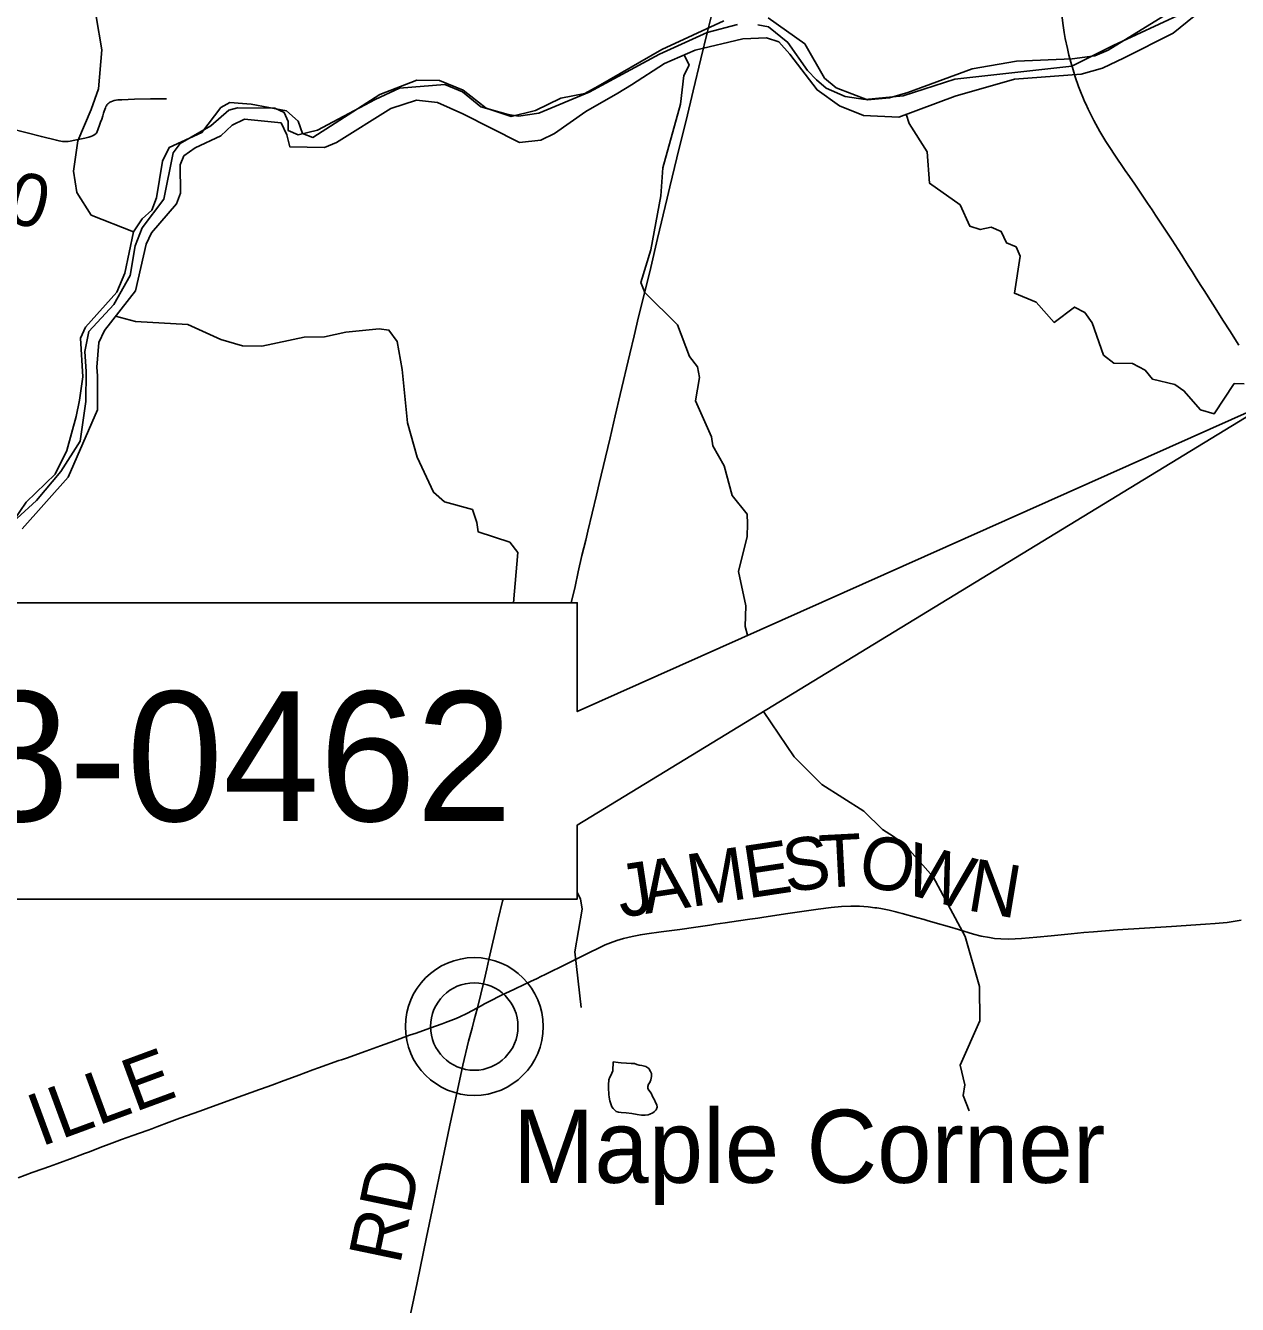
# Model space of a CAD drawing. Extents: x -1.4 to 35.4, y 0 to 22.
# Drawn here: x 13.799 to 15.107, y 13.734 to 15.116 of the extents above; entities that cross this region are included whole.
import ezdxf

# ---------------------------------------------------------------- set-up
doc = ezdxf.new("R2010")
doc.units = 0
for name, color, linetype in [('GM_X_County_Road', 7, 'Continuous'), ('GM_X_County_Road_Text', 7, 'Continuous'), ('GM_X_Major_River', 7, 'Continuous'), ('GM_X_Minor_Lake', 7, 'Continuous'), ('GM_X_Minor_River', 7, 'Continuous'), ('GM_X_Township_Road', 7, 'Continuous'), ('GM_X_Township_Road_Text', 7, 'Continuous'), ('GM_X_Unincorporated', 7, 'Continuous'), ('GM_X_Unincorporated_Location', 7, 'Continuous'), ('GM_X_Unincorporated_Text', 7, 'Continuous'), ('GM_X_US_Route', 7, 'Continuous'), ('SC_Scratch1', 7, 'Continuous'), ('SH_Data', 7, 'Continuous')]:
    doc.layers.add(name, color=color, linetype=linetype)

msp = doc.modelspace()

# ---------------------------------------------------------------- linework, layer by layer
at = {"layer": 'GM_X_County_Road'}
for points in [[(14.5347, 15.1076), (14.5396, 15.1278)], [(14.3878, 14.4922), (14.3919, 14.5098), (14.3954, 14.5255), (14.3994, 14.5431), (14.4035, 14.5599), (14.4059, 14.5696), (14.4151, 14.6083), (14.418, 14.621), (14.4248, 14.6494), (14.4298, 14.6705), (14.4353, 14.6941), (14.4407, 14.717), (14.4512, 14.7612), (14.4559, 14.7804), (14.4606, 14.8009), (14.4675, 14.8294), (14.4736, 14.8542), (14.4811, 14.8856), (14.4915, 14.9291), (14.4943, 14.9412), (14.5017, 14.9727), (14.5046, 14.9847), (14.5118, 15.013), (14.5195, 15.045), (14.5279, 15.0795), (14.5347, 15.1076)], [(14.2865, 14.0548), (14.2937, 14.0844), (14.2966, 14.097), (14.2989, 14.107), (14.309, 14.1505), (14.3136, 14.1698), (14.3142, 14.1722)], [(14.2865, 14.0548), (14.2904, 14.0569), (14.2942, 14.059), (14.2992, 14.0616), (14.3125, 14.0683), (14.326, 14.0747), (14.3378, 14.0802), (14.344, 14.0831), (14.3512, 14.0866), (14.3551, 14.0886), (14.3596, 14.0907), (14.3829, 14.1023), (14.3946, 14.1081), (14.404, 14.1129), (14.4112, 14.1165), (14.4135, 14.1175), (14.4179, 14.1196), (14.4223, 14.1217), (14.4244, 14.1227), (14.4301, 14.1251), (14.4372, 14.1275), (14.4444, 14.1296), (14.4535, 14.1318), (14.4626, 14.1337), (14.4694, 14.1348), (14.4848, 14.1369), (14.5051, 14.1395), (14.5223, 14.1419), (14.5376, 14.1442), (14.5395, 14.1445), (14.5431, 14.145), (14.5542, 14.1467), (14.5683, 14.1487), (14.5806, 14.1504), (14.5892, 14.1516), (14.5959, 14.1526), (14.6217, 14.1567), (14.6543, 14.1615), (14.6685, 14.1632), (14.6797, 14.1642), (14.6897, 14.1646), (14.699, 14.1644), (14.7084, 14.1638), (14.7158, 14.1629), (14.7177, 14.1626), (14.722, 14.1619), (14.7311, 14.1601), (14.7384, 14.1584), (14.7408, 14.1578), (14.745, 14.1568), (14.7606, 14.1525), (14.769, 14.1501), (14.772, 14.1492), (14.7809, 14.1467), (14.7964, 14.1421), (14.8059, 14.1392), (14.822, 14.1344), (14.8304, 14.1323), (14.8395, 14.1306), (14.8449, 14.1298), (14.8517, 14.1293), (14.8603, 14.1291), (14.8739, 14.1298), (14.8906, 14.1312), (14.906, 14.1327), (14.9276, 14.1348), (14.9413, 14.136), (14.9518, 14.1369), (14.9734, 14.1386), (14.9778, 14.139), (15.0069, 14.1409), (15.0361, 14.1427), (15.0726, 14.1451), (15.0831, 14.1458), (15.0961, 14.147), (15.1047, 14.1482), (15.1113, 14.1496)], [(13.7906, 13.8713), (13.8057, 13.8768), (13.8174, 13.8811), (13.8243, 13.8836), (13.8325, 13.8865), (13.85, 13.8929), (13.8576, 13.8957), (13.8622, 13.8974), (13.8675, 13.8993), (13.8738, 13.9018), (13.8819, 13.9049), (13.8888, 13.9076), (13.8976, 13.9108), (13.9022, 13.9125), (13.9145, 13.9169), (13.9216, 13.9193), (13.9309, 13.9226), (13.935, 13.9242), (13.9402, 13.9262), (13.9535, 13.9313), (13.9651, 13.9357), (13.9868, 13.9433), (13.9938, 13.9458), (14.0242, 13.9567), (14.0511, 13.9665), (14.0604, 13.9699), (14.0674, 13.9724), (14.075, 13.9751), (14.0937, 13.982), (14.1087, 13.9877), (14.1151, 13.9901), (14.1368, 13.9978), (14.1397, 13.9988), (14.145, 14.0006), (14.166, 14.0081), (14.1818, 14.0138), (14.197, 14.0193), (14.2133, 14.0251), (14.2204, 14.0276), (14.235, 14.0328), (14.2484, 14.0376), (14.2519, 14.0389), (14.2634, 14.0434), (14.2674, 14.0451), (14.2752, 14.0486), (14.2865, 14.0548)], [(14.1471, 13.4045), (14.1519, 13.4269), (14.1622, 13.4757), (14.169, 13.5079), (14.1771, 13.5456), (14.1836, 13.576), (14.186, 13.5875), (14.1992, 13.6508), (14.2084, 13.6952), (14.2143, 13.7238), (14.2214, 13.7578), (14.2316, 13.8071), (14.2377, 13.8363), (14.2449, 13.871), (14.2568, 13.9282), (14.2649, 13.9658), (14.2706, 13.9929), (14.2769, 14.0188), (14.2807, 14.033), (14.283, 14.0418), (14.2865, 14.0548)]]:
    msp.add_lwpolyline(points, dxfattribs=at)
at = {"layer": 'GM_X_Major_River'}
for points in [[(15.0966, 15.1552), (15.0377, 15.1075), (14.985, 15.0806), (14.9616, 15.0694), (14.9383, 15.0631), (14.8663, 15.0575), (14.8024, 15.0392), (14.7414, 15.0167), (14.7035, 15.0183), (14.6775, 15.0288), (14.6532, 15.0461), (14.624, 15.0847), (14.6118, 15.098), (14.5986, 15.1024), (14.5731, 15.1011), (14.5215, 15.089), (14.4885, 15.0746), (14.453, 15.0514), (14.4383, 15.0427), (14.4036, 15.0229), (14.3696, 14.999), (14.355, 14.9917), (14.3318, 14.9892), (14.2709, 15.0203), (14.2434, 15.0323), (14.2207, 15.0351), (14.1931, 15.0259), (14.1345, 14.9892), (14.1214, 14.9838), (14.0838, 14.9847), (14.0807, 14.9977), (14.0745, 15.0104), (14.0351, 15.0143), (14.0216, 15.0078), (14.0096, 14.9963), (13.9819, 14.9836), (13.9696, 14.9748), (13.9655, 14.965), (13.966, 14.9346), (13.9615, 14.9229), (13.9346, 14.8916), (13.929, 14.8795), (13.9175, 14.8289), (13.8839, 14.7863), (13.8779, 14.7732), (13.8757, 14.7466), (13.8763, 14.7371), (13.8762, 14.7006), (13.8445, 14.628), (13.7949, 14.5721)], [(15.078, 15.1572), (14.9674, 15.089), (14.9532, 15.0829), (14.9288, 15.0796), (14.8686, 15.0772), (14.8206, 15.0688), (14.7512, 15.0431), (14.7313, 15.0374), (14.7076, 15.0353), (14.6737, 15.0483), (14.6614, 15.0588), (14.6402, 15.0958), (14.6006, 15.1237)], [(14.5526, 15.1206), (14.4858, 15.0898), (14.4168, 15.05), (14.4026, 15.0423), (14.3766, 15.0372), (14.3493, 15.0238), (14.3229, 15.0172), (14.2958, 15.0262), (14.2711, 15.0457), (14.2455, 15.0562), (14.2212, 15.0564), (14.1813, 15.041), (14.1088, 14.9948), (14.0975, 14.9988), (14.0928, 15.0122), (14.0802, 15.0235), (14.0423, 15.0305), (14.0328, 15.0315), (14.0192, 15.0325), (14.0095, 15.0271), (13.9891, 15.0002), (13.9538, 14.9839), (13.9466, 14.9692), (13.94, 14.9295), (13.9351, 14.9163), (13.9247, 14.907), (13.9152, 14.8928), (13.9058, 14.8482), (13.897, 14.8278), (13.8634, 14.7898), (13.8578, 14.7778), (13.8603, 14.7363), (13.857, 14.7109), (13.8532, 14.6932), (13.8432, 14.6565), (13.8305, 14.631), (13.7994, 14.6009), (13.7856, 14.5807)]]:
    msp.add_lwpolyline(points, dxfattribs=at)
at = {"layer": 'GM_X_Minor_Lake'}
msp.add_lwpolyline([(14.4332, 13.9966), (14.4385, 13.9958), (14.4419, 13.9954), (14.4476, 13.9949), (14.4525, 13.9945), (14.4563, 13.9945), (14.4586, 13.9937), (14.4613, 13.9929), (14.4639, 13.9925), (14.4685, 13.9914), (14.4715, 13.9891), (14.4734, 13.986), (14.4745, 13.9837), (14.4745, 13.9807), (14.4737, 13.9769), (14.4726, 13.9742), (14.4714, 13.9723), (14.4706, 13.9697), (14.4706, 13.9678), (14.4717, 13.9659), (14.474, 13.9628), (14.4759, 13.9582), (14.4778, 13.9556), (14.4789, 13.9525), (14.4804, 13.9502), (14.4807, 13.9476), (14.4796, 13.9445), (14.4777, 13.9427), (14.4758, 13.9415), (14.4727, 13.94), (14.4708, 13.9393), (14.4678, 13.9389), (14.4636, 13.939), (14.459, 13.9397), (14.4533, 13.9405), (14.4472, 13.9414), (14.4419, 13.9418), (14.4389, 13.9422), (14.4362, 13.9429), (14.4332, 13.946), (14.4317, 13.9479), (14.4295, 13.9544), (14.4291, 13.9563), (14.4287, 13.9586), (14.4284, 13.9609), (14.4284, 13.9635), (14.428, 13.9662), (14.428, 13.9689), (14.428, 13.9715), (14.4281, 13.9734), (14.4285, 13.9753), (14.4285, 13.9772), (14.4296, 13.9799), (14.4308, 13.9825), (14.4316, 13.9844), (14.4327, 13.9867), (14.4332, 13.9966)], dxfattribs=at)
at = {"layer": 'GM_X_Minor_River'}
for points in [[(13.9152, 14.8928), (13.8695, 14.9109), (13.8541, 14.9352), (13.8504, 14.9584), (13.8552, 14.991), (13.8693, 15.0248), (13.8773, 15.0471), (13.8809, 15.0895), (13.8748, 15.1254), (13.8746, 15.1679), (13.8732, 15.1906)], [(14.5097, 15.0839), (14.515, 15.0728), (14.5094, 15.0615), (14.5057, 15.0305), (14.4868, 14.9618), (14.4846, 14.9318), (14.4739, 14.8732), (14.4629, 14.8381), (14.4672, 14.8274), (14.5025, 14.7924), (14.5154, 14.7583), (14.5243, 14.747), (14.5263, 14.7356), (14.522, 14.7102), (14.5394, 14.6715), (14.5407, 14.6616), (14.5531, 14.64), (14.5616, 14.6079), (14.5778, 14.5878), (14.578, 14.5775), (14.5777, 14.5638), (14.5685, 14.5261), (14.5765, 14.489), (14.5756, 14.4666), (14.578, 14.4572)], [(14.7496, 15.0197), (14.7527, 15.0099), (14.7721, 14.9791), (14.7748, 14.9452), (14.8077, 14.922), (14.8182, 14.899), (14.8295, 14.8953), (14.8413, 14.898), (14.8522, 14.8932), (14.8577, 14.8809), (14.8682, 14.8765), (14.8725, 14.8665), (14.8664, 14.8264), (14.8897, 14.8168), (14.9093, 14.795), (14.9313, 14.8116), (14.9422, 14.8057), (14.9503, 14.7944), (14.9625, 14.7596), (14.9737, 14.751), (14.9938, 14.7505), (15.0077, 14.7433), (15.0154, 14.7337), (15.0396, 14.7278), (15.0493, 14.7211), (15.0671, 14.7005), (15.0822, 14.6964), (15.1037, 14.7289), (15.1143, 14.7287)], [(13.8959, 14.8016), (13.9175, 14.7958), (13.9739, 14.7926), (14.0093, 14.7766), (14.033, 14.7695), (14.0539, 14.7694), (14.0996, 14.779), (14.1213, 14.7793), (14.1445, 14.7844), (14.1803, 14.7881), (14.1909, 14.7867), (14.1997, 14.7744), (14.2051, 14.7442), (14.2111, 14.6864), (14.2213, 14.6493), (14.2391, 14.6116), (14.251, 14.6011), (14.2812, 14.5928), (14.2858, 14.579), (14.2875, 14.5687), (14.3214, 14.5577), (14.3303, 14.5464), (14.3256, 14.4922)], [(14.5953, 14.3749), (14.6284, 14.326), (14.6585, 14.296), (14.7038, 14.2672), (14.7238, 14.2474), (14.7358, 14.2399), (14.7478, 14.2313), (14.7785, 14.1964), (14.8132, 14.1317), (14.8287, 14.0778), (14.8291, 14.0406), (14.8079, 13.9928), (14.8128, 13.9718), (14.811, 13.9601), (14.8175, 13.9436)], [(14.3943, 14.1792), (14.3978, 14.1726), (14.3995, 14.1615), (14.3916, 14.1154), (14.3987, 14.0552)]]:
    msp.add_lwpolyline(points, dxfattribs=at)
at = {"layer": 'GM_X_Township_Road'}
msp.add_lwpolyline([(13.7821, 15.0043), (13.8157, 14.9957), (13.832, 14.9917), (13.8349, 14.991), (13.8366, 14.9907), (13.8385, 14.9905), (13.8405, 14.9904), (13.8424, 14.9904), (13.8447, 14.9905), (13.8468, 14.9908), (13.8517, 14.9916), (13.8626, 14.9939), (13.8669, 14.995), (13.8692, 14.9958), (13.8709, 14.9964), (13.8725, 14.9973), (13.8739, 14.9983), (13.8747, 14.9991), (13.8754, 15.0001), (13.876, 15.0013), (13.8766, 15.003), (13.8774, 15.005), (13.8781, 15.007), (13.8789, 15.0092), (13.8797, 15.0112), (13.8808, 15.0146), (13.882, 15.0182), (13.8829, 15.0209), (13.8835, 15.023), (13.8842, 15.025), (13.8848, 15.0268), (13.8853, 15.028), (13.8859, 15.029), (13.8865, 15.0299), (13.8875, 15.0309), (13.8885, 15.0318), (13.8895, 15.0327), (13.8908, 15.0333), (13.8924, 15.034), (13.8944, 15.0346), (13.8963, 15.035), (13.8981, 15.0353), (13.8993, 15.0354), (13.9003, 15.0354), (13.9024, 15.0355), (13.9163, 15.036), (13.9335, 15.0364), (13.9509, 15.0365)], dxfattribs=at)
at = {"layer": 'GM_X_Unincorporated'}
for radius in [0.0744, 0.0472]:
    msp.add_circle((14.2831, 14.0346), radius, dxfattribs=at)
at = {"layer": 'GM_X_Unincorporated_Location'}
msp.add_line((14.2831, 14.0346), (14.2831, 14.0346), dxfattribs=at)
at = {"layer": 'GM_X_US_Route'}
for points in [[(14.92, 15.1082), (14.9186, 15.118), (14.9173, 15.1303), (14.9172, 15.1322), (14.9164, 15.1439), (14.916, 15.1576), (14.916, 15.188), (14.9159, 15.2091), (14.9159, 15.2317), (14.9159, 15.247), (14.9159, 15.2718), (14.9158, 15.2799), (14.9157, 15.2872)], [(14.9289, 15.0702), (14.9286, 15.0711), (14.9252, 15.0834), (14.9235, 15.0906), (14.9212, 15.1015), (14.92, 15.1082)], [(14.9421, 15.0337), (14.9408, 15.0365), (14.9376, 15.0444), (14.9356, 15.0496), (14.932, 15.0602), (14.9289, 15.0702)], [(15.1085, 14.7705), (15.0989, 14.7857), (15.0922, 14.7962), (15.0806, 14.8146), (15.0713, 14.8293), (15.0676, 14.835), (15.0627, 14.8429), (15.0584, 14.8498), (15.0547, 14.8555), (15.0504, 14.8623), (15.0471, 14.8676), (15.043, 14.8738), (15.0366, 14.8837), (15.0308, 14.8925), (15.0274, 14.8977), (15.0188, 14.9107), (15.0151, 14.9164), (15.0102, 14.9236), (14.9962, 14.9441), (14.9907, 14.9524), (14.9861, 14.959), (14.9742, 14.9765), (14.97, 14.9826), (14.9649, 14.9904), (14.9586, 15.001), (14.952, 15.0129), (14.946, 15.0251), (14.9433, 15.031), (14.9421, 15.0337)]]:
    msp.add_lwpolyline(points, dxfattribs=at)
at = {"layer": 'SC_Scratch1'}
for points in [[(15.0476, 15.1285), (14.9728, 15.0941), (14.9284, 15.0716), (14.8019, 15.0578), (14.7463, 15.0396), (14.7052, 15.0358), (14.6836, 15.039), (14.6631, 15.0479), (14.6525, 15.0571), (14.6431, 15.0671), (14.6217, 15.0972), (14.6009, 15.1141), (14.5892, 15.1165)], [(14.5892, 15.1165), (14.6009, 15.1141), (14.6217, 15.0972), (14.6431, 15.0671), (14.6525, 15.0571), (14.6631, 15.0479), (14.6836, 15.039), (14.7052, 15.0358), (14.7463, 15.0396), (14.8019, 15.0578), (14.9284, 15.0716), (14.9728, 15.0941), (15.0476, 15.1285)], [(14.5675, 15.1167), (14.5345, 15.1081), (14.4833, 15.0847), (14.4073, 15.0435), (14.3528, 15.0211), (14.3307, 15.0178), (14.3197, 15.0194), (14.2901, 15.0277), (14.2705, 15.0438), (14.2512, 15.0519), (14.2025, 15.0481), (14.1762, 15.0358), (14.114, 15.0025), (14.0931, 14.9977), (14.0821, 15.0023), (14.0821, 15.0118), (14.078, 15.0217), (14.0678, 15.0264), (14.0275, 15.0267), (14.018, 15.0241), (13.9985, 15.0072), (13.9657, 14.9881), (13.958, 14.9782), (13.9481, 14.9281), (13.9247, 14.8972), (13.9169, 14.8775), (13.9114, 14.8456), (13.894, 14.8142), (13.8668, 14.7851), (13.8625, 14.7635), (13.8642, 14.7418), (13.8636, 14.7095), (13.8576, 14.6666), (13.8368, 14.6338), (13.8104, 14.6028), (13.7893, 14.5832)], [(13.7893, 14.5832), (13.8104, 14.6028), (13.8368, 14.6338), (13.8576, 14.6666), (13.8636, 14.7095), (13.8642, 14.7418), (13.8625, 14.7635), (13.8668, 14.7851), (13.894, 14.8142), (13.9114, 14.8456), (13.9169, 14.8775), (13.9247, 14.8972), (13.9481, 14.9281), (13.958, 14.9782), (13.9657, 14.9881), (13.9985, 15.0072), (14.018, 15.0241), (14.0275, 15.0267), (14.0678, 15.0264), (14.078, 15.0217), (14.0821, 15.0118), (14.0821, 15.0023), (14.0931, 14.9977), (14.114, 15.0025), (14.1762, 15.0358), (14.2025, 15.0481), (14.2512, 15.0519), (14.2705, 15.0438), (14.2901, 15.0277), (14.3197, 15.0194), (14.3307, 15.0178), (14.3528, 15.0211), (14.4073, 15.0435), (14.4833, 15.0847), (14.5345, 15.1081), (14.5675, 15.1167)]]:
    msp.add_lwpolyline(points, dxfattribs=at)
at = {"layer": 'SH_Data'}
msp.add_lwpolyline([(13.1243, 14.4922), (14.3943, 14.4922), (14.3943, 14.3747), (15.1442, 14.7096), (14.3943, 14.2522), (14.3943, 14.1722), (13.1243, 14.1722)], close=True, dxfattribs=at)

# ---------------------------------------------------------------- texts
at = {"layer": 'GM_X_County_Road_Text'}
for s, height, rotation, p in [('S', 0.0568, 7.9944, (14.6202, 14.1791)), ('T', 0.0568, 2.9454, (14.6568, 14.1843)), ('O', 0.0568, 351.1677, (14.6962, 14.1867)), ('M', 0.0568, 8.6096, (14.5173, 14.1636)), ('E', 0.0568, 8.5816, (14.5783, 14.1728)), ('W', 0.0568, 344.4403, (14.7439, 14.1794)), ('J', 0.0568, 8.6111, (14.4415, 14.1521)), ('A', 0.0568, 8.6077, (14.4679, 14.1561)), ('N', 0.0568, 350.5162, (14.8137, 14.1603)), ('E', 0.0568, 20.2525, (13.9165, 13.942)), ('L', 0.0568, 20.2486, (13.8766, 13.9273)), ('I', 0.0568, 20.2472, (13.8149, 13.9045)), ('L', 0.0568, 20.2525, (13.8368, 13.9126)), ('RD', 0.05682, 78.2123, (14.2028, 13.7764))]:
    msp.add_text(s, height=height, rotation=rotation, dxfattribs=at).set_placement(p)
at = {"layer": 'GM_X_Township_Road_Text'}
msp.add_text('T-70', height=0.05682, rotation=345.7946, dxfattribs=at).set_placement((13.6643, 14.9328))
at = {"layer": 'GM_X_Unincorporated_Text'}
msp.add_text('Maple Corner', height=0.078977, rotation=0, dxfattribs=at).set_placement((14.3248, 13.8658))
at = {"layer": 'SH_Data'}
msp.add_text('GRE-68-0462', height=0.14, dxfattribs=at).set_placement((13.1691, 14.2564))

doc.saveas('drawing.dxf')
